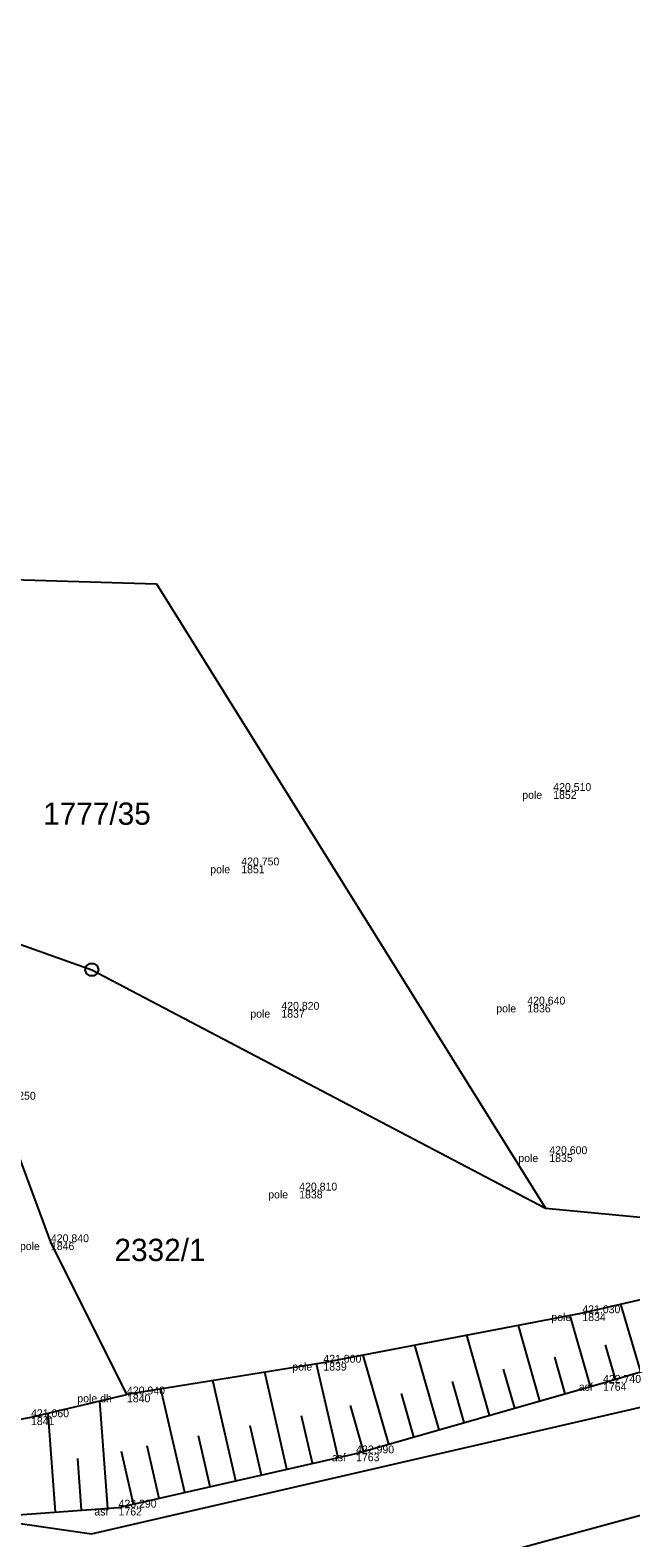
# Model space of a CAD drawing. Extents: x -747792 to -745414, y -1093712 to -1091463.
# Drawn here: x -746636.4 to -746613.5, y -1092632.1 to -1092574.5 of the extents above; entities that cross this region are included whole.
import ezdxf

# ---------------------------------------------------------------- set-up
doc = ezdxf.new("R2010")
doc.units = 0
for name, color, linetype in [('Doplňující texty', 7, 'Continuous'), ('Hladina', 7, 'Continuous'), ('Koleje_dopravní prvky', 7, 'Continuous'), ('Nivelační značky_hrany', 7, 'Continuous'), ('Pracovní_bod JDTM STC_VC - výška', 7, 'Continuous'), ('Pracovní_bod PPBP', 7, 'Continuous'), ('Rozhraní ploch', 7, 'Continuous'), ('Stromy_porost', 7, 'Continuous'), ('Výškopis', 7, 'Continuous')]:
    doc.layers.add(name, color=color, linetype=linetype)

msp = doc.modelspace()

# ---------------------------------------------------------------- linework, layer by layer
at = {"layer": 'Doplňující texty'}
msp.add_lwpolyline([(-746634.005, -1092610.13), (-746633.88, -1092610.225), (-746633.83, -1092610.37), (-746633.88, -1092610.515), (-746634.005, -1092610.61), (-746634.155, -1092610.61), (-746634.28, -1092610.515), (-746634.33, -1092610.37), (-746634.28, -1092610.225), (-746634.155, -1092610.13)], close=True, dxfattribs=at)
msp.add_lwpolyline([(-746634.105, -1092610.37), (-746634.055, -1092610.37)], dxfattribs=at)
at = {"layer": 'Hladina'}
for p, q in [((-746616.48, -1092603.55), (-746616.48, -1092603.55)), ((-746628.38, -1092606.39), (-746628.38, -1092606.39)), ((-746626.85, -1092611.9), (-746626.85, -1092611.9)), ((-746617.47, -1092611.7), (-746617.47, -1092611.7)), ((-746616.63, -1092617.41), (-746616.63, -1092617.41)), ((-746626.17, -1092618.8), (-746626.17, -1092618.8)), ((-746635.64, -1092620.77), (-746635.64, -1092620.77)), ((-746615.37, -1092623.48), (-746615.37, -1092623.48)), ((-746625.25, -1092625.37), (-746625.25, -1092625.37)), ((-746614.58, -1092626.14), (-746614.58, -1092626.14)), ((-746632.74, -1092626.58), (-746632.74, -1092626.58)), ((-746636.4, -1092627.45), (-746636.4, -1092627.45)), ((-746624, -1092628.83), (-746624, -1092628.83)), ((-746633.06, -1092630.9), (-746633.06, -1092630.9))]:
    msp.add_line(p, q, dxfattribs=at)
at = {"layer": 'Nivelační značky_hrany'}
msp.add_lwpolyline([(-746646.08, -1092622.58), (-746645.42, -1092626.74), (-746642.99, -1092629.82), (-746639.53, -1092631.37), (-746633.06, -1092630.9), (-746624, -1092628.83), (-746614.58, -1092626.14), (-746604.52, -1092623.18), (-746602.28, -1092622.35)], dxfattribs=at)
at = {"layer": 'Pracovní_bod JDTM STC_VC - výška'}
for points in [[(-746632.74, -1092626.58), (-746635.64, -1092620.77), (-746637.67, -1092615.33), (-746638.38, -1092607.28), (-746642.34, -1092583.46), (-746643.39, -1092573.07), (-746645.13, -1092563.74), (-746647.06, -1092557.12), (-746650.52, -1092546.83), (-746656.13, -1092532.17), (-746659.53, -1092519.12), (-746666.48, -1092509.53), (-746671.18, -1092501.38)], [(-746593.1, -1092618.4), (-746602.06, -1092620.21), (-746608.18, -1092621.82), (-746615.37, -1092623.48), (-746625.25, -1092625.37), (-746632.74, -1092626.58)]]:
    msp.add_lwpolyline(points, dxfattribs=at)
at = {"layer": 'Pracovní_bod PPBP'}
for points in [[(-746642.4, -1092621.5), (-746641.58, -1092624.29), (-746641.28, -1092626.53), (-746639.31, -1092627.98), (-746636.4, -1092627.45), (-746632.74, -1092626.58)], [(-746613.144, -1092625.718), (-746613.903, -1092623.141)], [(-746616.987, -1092626.827), (-746617.81, -1092623.947)], [(-746615.064, -1092626.278), (-746615.838, -1092623.569)], [(-746618.91, -1092627.377), (-746619.782, -1092624.324)], [(-746622.757, -1092628.475), (-746623.727, -1092625.079)], [(-746620.834, -1092627.926), (-746621.754, -1092624.701)], [(-746616.026, -1092626.553), (-746616.425, -1092625.155)], [(-746614.104, -1092626), (-746614.491, -1092624.683)], [(-746626.639, -1092629.433), (-746627.485, -1092625.731)], [(-746624.689, -1092628.987), (-746625.506, -1092625.411)], [(-746617.949, -1092627.102), (-746618.373, -1092625.619)], [(-746628.589, -1092629.878), (-746629.463, -1092626.051)], [(-746619.872, -1092627.651), (-746620.32, -1092626.082)], [(-746633.472, -1092630.93), (-746633.771, -1092626.825)], [(-746630.539, -1092630.324), (-746631.442, -1092626.37)], [(-746621.795, -1092628.2), (-746622.268, -1092626.545)], [(-746635.467, -1092631.075), (-746635.742, -1092627.294)], [(-746625.664, -1092629.21), (-746626.08, -1092627.391)], [(-746623.718, -1092628.75), (-746624.216, -1092627.008)], [(-746627.614, -1092629.656), (-746628.044, -1092627.773)], [(-746631.513, -1092630.547), (-746631.972, -1092628.538)], [(-746629.564, -1092630.101), (-746630.008, -1092628.156)], [(-746634.47, -1092631.002), (-746634.613, -1092629.031)], [(-746632.488, -1092630.769), (-746632.949, -1092628.754)]]:
    msp.add_lwpolyline(points, dxfattribs=at)
at = {"layer": 'Stromy_porost'}
for points in [[(-746641.76, -1092595.34), (-746631.61, -1092595.64)], [(-746631.61, -1092595.64), (-746616.78, -1092619.47)], [(-746640.52, -1092608.08), (-746634.08, -1092610.37)], [(-746634.08, -1092610.37), (-746616.78, -1092619.47)], [(-746616.78, -1092619.47), (-746602.85, -1092620.8)], [(-746634.09, -1092631.9), (-746605.32, -1092625.26)], [(-746635.55, -1092637.3), (-746607.79, -1092629.73)], [(-746638.23, -1092631.3), (-746634.09, -1092631.9)]]:
    msp.add_lwpolyline(points, dxfattribs=at)

# ---------------------------------------------------------------- texts
at = {"layer": 'Koleje_dopravní prvky'}
for s, p in [('1777/35', (-746635.939, -1092604.84)), ('2332/1', (-746633.218, -1092621.49))]:
    msp.add_text(s, height=0.85, dxfattribs=at).set_placement(p)
at = {"layer": 'Rozhraní ploch'}
for s, p in [(' pole', (-746617.774, -1092603.85)), ('1852', (-746616.48, -1092603.85)), (' pole', (-746629.674, -1092606.69)), ('1851', (-746628.38, -1092606.69)), (' pole', (-746628.144, -1092612.2)), ('1837', (-746626.85, -1092612.2)), (' pole', (-746618.764, -1092612)), ('1836', (-746617.47, -1092612)), (' pole', (-746617.924, -1092617.71)), ('1835', (-746616.63, -1092617.71)), (' pole', (-746627.464, -1092619.1)), ('1838', (-746626.17, -1092619.1)), (' pole', (-746636.934, -1092621.07)), ('1846', (-746635.64, -1092621.07)), (' pole', (-746616.664, -1092623.78)), ('1834', (-746615.37, -1092623.78)), (' pole', (-746626.544, -1092625.67)), ('1839', (-746625.25, -1092625.67)), (' asf', (-746615.617, -1092626.44)), ('1764', (-746614.58, -1092626.44)), (' pole.dh', (-746634.745, -1092626.88)), ('1840', (-746632.74, -1092626.88)), ('1841', (-746636.4, -1092627.75)), (' asf', (-746625.037, -1092629.13)), ('1763', (-746624, -1092629.13)), (' asf', (-746634.097, -1092631.2)), ('1762', (-746633.06, -1092631.2))]:
    msp.add_text(s, height=0.3, dxfattribs=at).set_placement(p)
at = {"layer": 'Výškopis'}
for s, p in [('420,510', (-746616.48, -1092603.55)), ('420,750', (-746628.38, -1092606.39)), ('420,820', (-746626.85, -1092611.9)), ('420,640', (-746617.47, -1092611.7)), ('421,250', (-746637.67, -1092615.33)), ('420,600', (-746616.63, -1092617.41)), ('420,810', (-746626.17, -1092618.8)), ('420,840', (-746635.64, -1092620.77)), ('421,030', (-746615.37, -1092623.48)), ('421,000', (-746625.25, -1092625.37)), ('420,940', (-746632.74, -1092626.58)), ('422,740', (-746614.58, -1092626.14)), ('421,060', (-746636.4, -1092627.45)), ('422,990', (-746624, -1092628.83)), ('423,290', (-746633.06, -1092630.9))]:
    msp.add_text(s, height=0.3, dxfattribs=at).set_placement(p)

doc.saveas('drawing.dxf')
